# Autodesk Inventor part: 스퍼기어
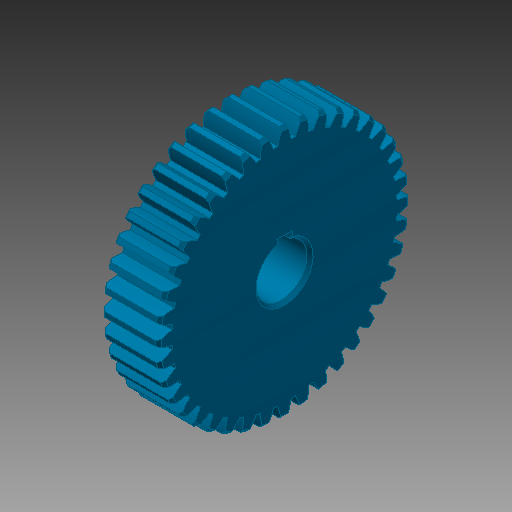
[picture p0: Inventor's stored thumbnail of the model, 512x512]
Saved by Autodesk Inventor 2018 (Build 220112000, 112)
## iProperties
Created: 2018-11
Part Number: 스퍼기어
Material: 알루미늄 6061
Document SubType Name: Modeling
Designer: mduedu
Categories: <?xml version="1.0" encoding="UTF-16"?> <MemberInstance><Categories><FamilyTemplate><FamilyTemplateParameter ValueType="xs:double" Id="1" ObjectReferenceKey="da
Density: 1 g/cm^3
Appearance: 하늘색 중간
CustomPartVersion: 1
Author: mduedu
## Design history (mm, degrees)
sketch "Sketch1"
  geometry: C1 r 42 at (0, 0)
  constraints: 1 centre point
  dimensions: "d0" = 83.99905 diameter of C1 (= da_da)
extrude "Extrusion1" new body sketch "Sketch1" distance "d1" = 19 (= da_b); taper "d2" = 0 deg
workplane "Work Plane2"
sketch "Sketch2"
  geometry: C1 r 42 at (0, 0) reference; C2 r 40.05 at (0, 0)
  constraints: 1 centre point, 1 coincident
  dimensions: "d3" = 80.10038 diameter of C2 (= da_dw)
feature "피치 지름" sketch "Sketch2" dims "d4" = 10, "d5" = 0
workplane "Work Plane8"
workplane "Work Plane9"
feature "스퍼 기어" dims "da_b" = 19, "da_d" = 80, "da_aw" = 80.10038, "da_da" = 83.99905, "da_df" = 75, "da_dw" = 80.10038, angle "da_beta" = 0 deg, "da_lefttooth" = 0, "da_righttooth" = 0
sketch "스케치3"
  geometry: L1 (-42, 19)-(42, 19) reference; L2 (42, 19)-(42, 0) reference; L3 (42, 0)-(-42, 0) reference; L4 (-42, 0)-(-42, 19) reference; L5 (0, 0)-(0, 19); L6 (42, 0)-(41, 0); L7 (42, 1)-(42, 0); L8 (42, 19)-(41, 19); L9 (42, 18)-(42, 19); L10 (41, 19)-(42, 18); L11 (41, 0)-(42, 1)
  constraints: 14 end point, 2 horizontal, 2 vertical, 1 midpoint
  dimensions: "d49" = 1 distance from line of L8.end L2; "d50" = 1 horizontal distance of L8.end L9.start; "d51" = 1 horizontal distance of L6.end L7.start; "d52" = 1 horizontal distance of L6.end L7.start
revolve "회전1" sketch "스케치3" stored, may be unused: angle "d53" = 90 deg
sketch "스케치4"
  geometry: L1 (-2.5, 8.124)-(2.5, 8.124); L2 (2.5, 8.124)-(2.5, 10.8); L3 (2.5, 10.8)-(-2.5, 10.8); L4 (-2.5, 10.8)-(-2.5, 8.124); A1 r 8.5 centre (0, 0) between (-2.5, 8.124) and (2.5, 8.124); 1 further point
  constraints: 8 end point, 2 parallel, 2 point on circle, 1 centre point, 1 coincident, 1 horizontal, 1 perpendicular
  dimensions: "d54" = 17 diameter of A1; "d56" = 19.3 dimension on A1 L3; "d57" = 5 distance of L2.end L3.end
extrude "돌출2" cut sketch "스케치4" extent not by distance; stored distance "d58" = 10; taper "d59" = 0 deg
chamfer "모따기1" distance "d60" = 1; stored, may be unused: second distance "d61" = 2, angle "d62" = 45 deg
sketch "스케치5"
  geometry: C1 r 17.5 at (0, 0); C2 r 28.5 at (0, 0); 1 further point
  constraints: 2 centre point, 2 coincident
  dimensions: "d63" = 35 diameter of C1; "d64" = 57 diameter of C2
extrude "돌출3" cut sketch "스케치5" distance "d65" = 9.5; taper "d66" = 0 deg
fillet "모깎기1" dims "d67" = 3
body "Solid1"
body "Srf1"
node "절단 모서리 투영1"
other parameters: "d16" = 80.10038 (= da_aw), "d17" = 0, "d34" = 4.5 deg (computed from da_z), "d39" = 0, "d41" = 0, "d43" = 80.10038 (= da_aw), "d46" = 80.10038 (= da_aw), "d47" = 0, "d48" = 0
